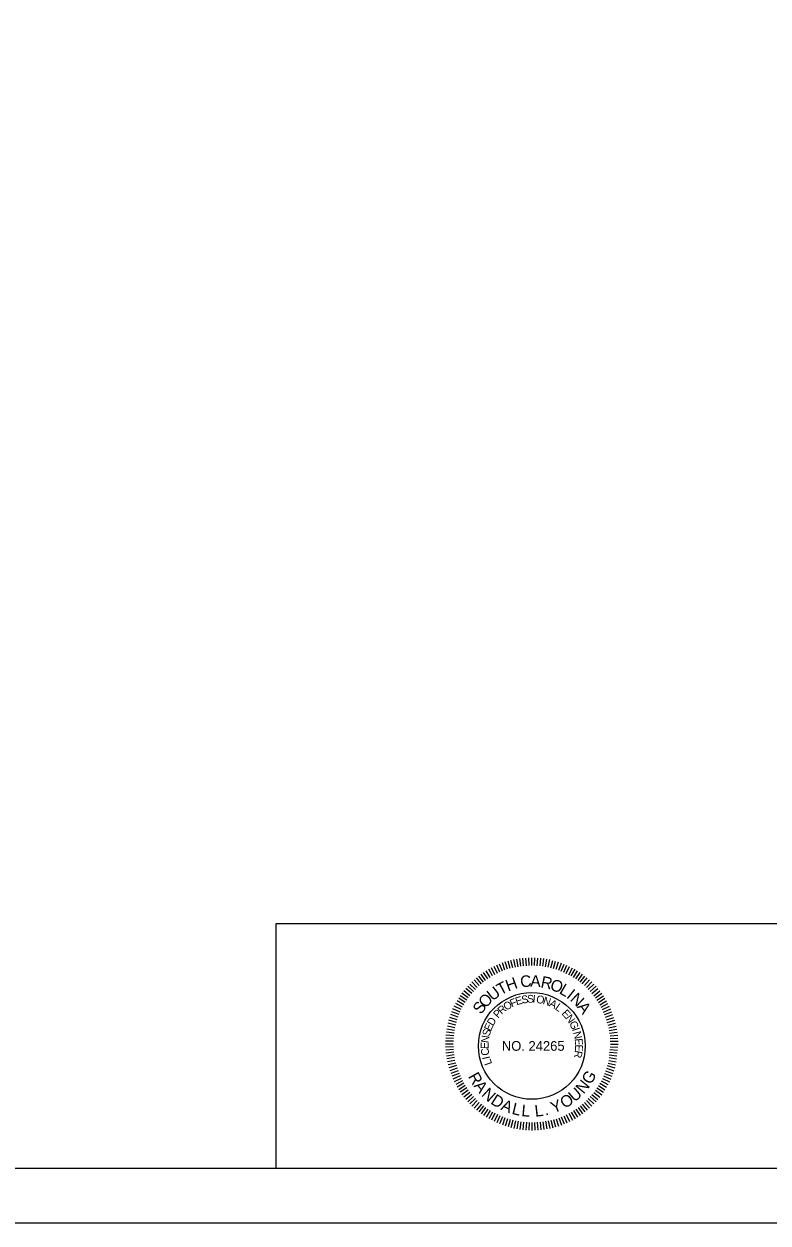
# Model space of a CAD drawing. Extents: x -796 to 2793, y -4650 to 4425.
# Drawn here: x 1879 to 2221, y -3500 to -2950 of the extents above; entities that cross this region are included whole.
import ezdxf

# ---------------------------------------------------------------- set-up
doc = ezdxf.new("R2010")
doc.units = 0
for name, color, linetype in [('RD_EX_Misc', 7, 'Continuous'), ('RD_HC_CL', 7, 'Continuous'), ('RD_HC_Data', 7, 'Continuous')]:
    doc.layers.add(name, color=color, linetype=linetype)

msp = doc.modelspace()

# ---------------------------------------------------------------- linework, layer by layer
at = {"layer": 'RD_EX_Misc'}
for p, q in [((2096.52, -3385.54), (2094.96, -3382.34)), ((2096.52, -3385.54), (2094.96, -3382.34)), ((2097.64, -3384.97), (2096.19, -3381.71)), ((2097.64, -3384.97), (2096.19, -3381.71)), ((2098.81, -3384.52), (2097.48, -3381.22)), ((2098.81, -3384.52), (2097.48, -3381.22)), ((2099.98, -3384.07), (2098.77, -3380.72)), ((2099.98, -3384.07), (2098.77, -3380.72)), ((2101.16, -3383.62), (2100.06, -3380.23)), ((2101.16, -3383.62), (2100.06, -3380.23)), ((2102.37, -3383.29), (2101.39, -3379.87)), ((2102.37, -3383.29), (2101.39, -3379.87)), ((2103.59, -3382.96), (2102.73, -3379.51)), ((2103.59, -3382.96), (2102.73, -3379.51)), ((2104.8, -3382.64), (2104.06, -3379.16)), ((2104.8, -3382.64), (2104.06, -3379.16)), ((2106.05, -3382.44), (2105.43, -3378.94)), ((2106.05, -3382.44), (2105.43, -3378.94)), ((2107.29, -3382.25), (2106.79, -3378.72)), ((2107.29, -3382.25), (2106.79, -3378.72)), ((2108.53, -3382.05), (2108.16, -3378.51)), ((2108.53, -3382.05), (2108.16, -3378.51)), ((2109.79, -3381.98), (2109.54, -3378.44)), ((2109.79, -3381.98), (2109.54, -3378.44)), ((2111.04, -3381.92), (2110.92, -3378.36)), ((2111.04, -3381.92), (2110.92, -3378.36)), ((2112.3, -3381.85), (2112.3, -3378.29)), ((2112.3, -3381.85), (2112.3, -3378.29)), ((2113.55, -3381.92), (2113.68, -3378.36)), ((2113.55, -3381.92), (2113.68, -3378.36)), ((2114.81, -3381.98), (2115.06, -3378.44)), ((2114.81, -3381.98), (2115.06, -3378.44)), ((2116.07, -3382.05), (2116.44, -3378.51)), ((2116.07, -3382.05), (2116.44, -3378.51)), ((2117.31, -3382.25), (2117.8, -3378.72)), ((2117.31, -3382.25), (2117.8, -3378.72)), ((2118.55, -3382.44), (2119.17, -3378.94)), ((2118.55, -3382.44), (2119.17, -3378.94)), ((2119.79, -3382.64), (2120.53, -3379.16)), ((2119.79, -3382.64), (2120.53, -3379.16)), ((2119.79, -3382.64), (2120.53, -3379.16)), ((2121.01, -3382.96), (2121.87, -3379.51)), ((2121.01, -3382.96), (2121.87, -3379.51)), ((2121.01, -3382.96), (2121.87, -3379.51)), ((2122.22, -3383.29), (2123.2, -3379.87)), ((2122.22, -3383.29), (2123.2, -3379.87)), ((2122.22, -3383.29), (2123.2, -3379.87)), ((2123.44, -3383.62), (2124.54, -3380.23)), ((2123.44, -3383.62), (2124.54, -3380.23)), ((2123.44, -3383.62), (2124.54, -3380.23)), ((2124.61, -3384.07), (2125.83, -3380.72)), ((2124.61, -3384.07), (2125.83, -3380.72)), ((2124.61, -3384.07), (2125.83, -3380.72)), ((2125.78, -3384.52), (2127.12, -3381.22)), ((2125.78, -3384.52), (2127.12, -3381.22)), ((2125.78, -3384.52), (2127.12, -3381.22)), ((2126.96, -3384.97), (2128.41, -3381.71)), ((2126.96, -3384.97), (2128.41, -3381.71)), ((2126.96, -3384.97), (2128.41, -3381.71)), ((2128.08, -3385.54), (2129.64, -3382.34)), ((2128.08, -3385.54), (2129.64, -3382.34)), ((2128.08, -3385.54), (2129.64, -3382.34)), ((2089.16, -3390.32), (2086.87, -3387.59)), ((2089.16, -3390.32), (2086.87, -3387.59)), ((2090.13, -3389.53), (2087.94, -3386.72)), ((2090.13, -3389.53), (2087.94, -3386.72)), ((2091.11, -3388.73), (2089.02, -3385.85)), ((2091.11, -3388.73), (2089.02, -3385.85)), ((2092.17, -3388.05), (2090.18, -3385.1)), ((2092.17, -3388.05), (2090.18, -3385.1)), ((2093.22, -3387.37), (2091.34, -3384.35)), ((2093.22, -3387.37), (2091.34, -3384.35)), ((2094.28, -3386.68), (2092.5, -3383.6)), ((2094.28, -3386.68), (2092.5, -3383.6)), ((2095.4, -3386.11), (2093.73, -3382.97)), ((2095.4, -3386.11), (2093.73, -3382.97)), ((2129.2, -3386.11), (2130.87, -3382.97)), ((2129.2, -3386.11), (2130.87, -3382.97)), ((2129.2, -3386.11), (2130.87, -3382.97)), ((2130.32, -3386.68), (2132.1, -3383.6)), ((2130.32, -3386.68), (2132.1, -3383.6)), ((2130.32, -3386.68), (2132.1, -3383.6)), ((2131.38, -3387.37), (2133.26, -3384.35)), ((2131.38, -3387.37), (2133.26, -3384.35)), ((2131.38, -3387.37), (2133.26, -3384.35)), ((2132.43, -3388.05), (2134.42, -3385.1)), ((2132.43, -3388.05), (2134.42, -3385.1)), ((2132.43, -3388.05), (2134.42, -3385.1)), ((2133.48, -3388.73), (2135.58, -3385.85)), ((2133.48, -3388.73), (2135.58, -3385.85)), ((2133.48, -3388.73), (2135.58, -3385.85)), ((2134.46, -3389.53), (2136.65, -3386.72)), ((2134.46, -3389.53), (2136.65, -3386.72)), ((2134.46, -3389.53), (2136.65, -3386.72)), ((2135.44, -3390.32), (2137.72, -3387.59)), ((2135.44, -3390.32), (2137.72, -3387.59)), ((2135.44, -3390.32), (2137.72, -3387.59)), ((2084.72, -3394.75), (2082, -3392.47)), ((2084.72, -3394.75), (2082, -3392.47)), ((2085.51, -3393.78), (2082.87, -3391.4)), ((2085.51, -3393.78), (2082.87, -3391.4)), ((2086.4, -3392.89), (2083.84, -3390.42)), ((2086.4, -3392.89), (2083.84, -3390.42)), ((2087.29, -3392), (2084.82, -3389.44)), ((2087.29, -3392), (2084.82, -3389.44)), ((2088.18, -3391.11), (2085.8, -3388.46)), ((2088.18, -3391.11), (2085.8, -3388.46)), ((2136.42, -3391.11), (2138.8, -3388.46)), ((2136.42, -3391.11), (2138.8, -3388.46)), ((2136.42, -3391.11), (2138.8, -3388.46)), ((2137.31, -3392), (2139.78, -3389.44)), ((2137.31, -3392), (2139.78, -3389.44)), ((2137.31, -3392), (2139.78, -3389.44)), ((2138.2, -3392.89), (2140.75, -3390.42)), ((2138.2, -3392.89), (2140.75, -3390.42)), ((2138.2, -3392.89), (2140.75, -3390.42)), ((2139.08, -3393.78), (2141.73, -3391.4)), ((2139.08, -3393.78), (2141.73, -3391.4)), ((2139.08, -3393.78), (2141.73, -3391.4)), ((2139.88, -3394.75), (2142.6, -3392.47)), ((2139.88, -3394.75), (2142.6, -3392.47)), ((2139.88, -3394.75), (2142.6, -3392.47)), ((2081.08, -3399.87), (2078, -3398.09)), ((2081.08, -3399.87), (2078, -3398.09)), ((2081.77, -3398.82), (2078.75, -3396.93)), ((2081.77, -3398.82), (2078.75, -3396.93)), ((2082.45, -3397.76), (2079.5, -3395.78)), ((2082.45, -3397.76), (2079.5, -3395.78)), ((2083.14, -3396.71), (2080.26, -3394.62)), ((2083.14, -3396.71), (2080.26, -3394.62)), ((2083.93, -3395.73), (2081.13, -3393.54)), ((2083.93, -3395.73), (2081.13, -3393.54)), ((2140.67, -3395.73), (2143.47, -3393.54)), ((2140.67, -3395.73), (2143.47, -3393.54)), ((2140.67, -3395.73), (2143.47, -3393.54)), ((2141.46, -3396.71), (2144.34, -3394.62)), ((2141.46, -3396.71), (2144.34, -3394.62)), ((2141.46, -3396.71), (2144.34, -3394.62)), ((2142.14, -3397.76), (2145.09, -3395.78)), ((2142.14, -3397.76), (2145.09, -3395.78)), ((2142.14, -3397.76), (2145.09, -3395.78)), ((2142.83, -3398.82), (2145.84, -3396.93)), ((2142.83, -3398.82), (2145.84, -3396.93)), ((2142.83, -3398.82), (2145.84, -3396.93)), ((2143.51, -3399.87), (2146.6, -3398.09)), ((2143.51, -3399.87), (2146.6, -3398.09)), ((2143.51, -3399.87), (2146.6, -3398.09)), ((2078.47, -3405.58), (2075.13, -3404.37)), ((2078.47, -3405.58), (2075.13, -3404.37)), ((2078.92, -3404.41), (2075.62, -3403.08)), ((2078.92, -3404.41), (2075.62, -3403.08)), ((2079.37, -3403.24), (2076.12, -3401.79)), ((2079.37, -3403.24), (2076.12, -3401.79)), ((2079.94, -3402.11), (2076.74, -3400.56)), ((2079.94, -3402.11), (2076.74, -3400.56)), ((2080.51, -3400.99), (2077.37, -3399.33)), ((2080.51, -3400.99), (2077.37, -3399.33)), ((2144.09, -3400.99), (2147.22, -3399.33)), ((2144.09, -3400.99), (2147.22, -3399.33)), ((2144.09, -3400.99), (2147.22, -3399.33)), ((2144.66, -3402.11), (2147.85, -3400.56)), ((2144.66, -3402.11), (2147.85, -3400.56)), ((2144.66, -3402.11), (2147.85, -3400.56)), ((2145.23, -3403.24), (2148.48, -3401.79)), ((2145.23, -3403.24), (2148.48, -3401.79)), ((2145.23, -3403.24), (2148.48, -3401.79)), ((2145.68, -3404.41), (2148.97, -3403.08)), ((2145.68, -3404.41), (2148.97, -3403.08)), ((2145.68, -3404.41), (2148.97, -3403.08)), ((2146.13, -3405.58), (2149.47, -3404.37)), ((2146.13, -3405.58), (2149.47, -3404.37)), ((2146.13, -3405.58), (2149.47, -3404.37)), ((2077.04, -3410.4), (2073.56, -3409.66)), ((2077.04, -3410.4), (2073.56, -3409.66)), ((2077.37, -3409.19), (2073.92, -3408.33)), ((2077.37, -3409.19), (2073.92, -3408.33)), ((2077.69, -3407.97), (2074.27, -3406.99)), ((2077.69, -3407.97), (2074.27, -3406.99)), ((2078.02, -3406.76), (2074.63, -3405.66)), ((2078.02, -3406.76), (2074.63, -3405.66)), ((2146.58, -3406.76), (2149.96, -3405.66)), ((2146.58, -3406.76), (2149.96, -3405.66)), ((2146.58, -3406.76), (2149.96, -3405.66)), ((2146.9, -3407.97), (2150.32, -3406.99)), ((2146.9, -3407.97), (2150.32, -3406.99)), ((2146.9, -3407.97), (2150.32, -3406.99)), ((2147.23, -3409.19), (2150.68, -3408.33)), ((2147.23, -3409.19), (2150.68, -3408.33)), ((2147.23, -3409.19), (2150.68, -3408.33)), ((2147.56, -3410.4), (2151.04, -3409.66)), ((2147.56, -3410.4), (2151.04, -3409.66)), ((2147.56, -3410.4), (2151.04, -3409.66)), ((2076.38, -3415.38), (2072.84, -3415.14)), ((2076.38, -3415.38), (2072.84, -3415.14)), ((2076.45, -3414.13), (2072.91, -3413.76)), ((2076.45, -3414.13), (2072.91, -3413.76)), ((2076.65, -3412.89), (2073.13, -3412.39)), ((2076.65, -3412.89), (2073.13, -3412.39)), ((2076.84, -3411.64), (2073.34, -3411.03)), ((2076.84, -3411.64), (2073.34, -3411.03)), ((2147.75, -3411.64), (2151.25, -3411.03)), ((2147.75, -3411.64), (2151.25, -3411.03)), ((2147.75, -3411.64), (2151.25, -3411.03)), ((2147.95, -3412.89), (2151.47, -3412.39)), ((2147.95, -3412.89), (2151.47, -3412.39)), ((2147.95, -3412.89), (2151.47, -3412.39)), ((2148.15, -3414.13), (2151.69, -3413.76)), ((2148.15, -3414.13), (2151.69, -3413.76)), ((2148.15, -3414.13), (2151.69, -3413.76)), ((2148.21, -3415.38), (2151.76, -3415.14)), ((2148.21, -3415.38), (2151.76, -3415.14)), ((2148.21, -3415.38), (2151.76, -3415.14)), ((2076.25, -3417.9), (2072.69, -3417.9)), ((2076.25, -3417.9), (2072.69, -3417.9)), ((2076.32, -3416.64), (2072.77, -3416.52)), ((2076.32, -3416.64), (2072.77, -3416.52)), ((2076.32, -3419.15), (2072.77, -3419.28)), ((2076.32, -3419.15), (2072.77, -3419.28)), ((2076.38, -3420.41), (2072.84, -3420.66)), ((2076.38, -3420.41), (2072.84, -3420.66)), ((2148.08, -3420.4), (2151.61, -3420.65)), ((2148.08, -3420.4), (2151.61, -3420.65)), ((2148.21, -3419.15), (2151.76, -3419.27)), ((2148.21, -3419.15), (2151.76, -3419.27)), ((2148.28, -3416.64), (2151.83, -3416.52)), ((2148.28, -3416.64), (2151.83, -3416.52)), ((2148.28, -3416.64), (2151.83, -3416.52)), ((2148.34, -3417.9), (2151.9, -3417.9)), ((2148.34, -3417.9), (2151.9, -3417.9)), ((2148.34, -3417.9), (2151.9, -3417.9)), ((2076.45, -3421.66), (2072.91, -3422.04)), ((2076.45, -3421.66), (2072.91, -3422.04)), ((2076.65, -3422.91), (2073.13, -3423.4)), ((2076.65, -3422.91), (2073.13, -3423.4)), ((2076.84, -3424.15), (2073.34, -3424.76)), ((2076.84, -3424.15), (2073.34, -3424.76)), ((2077.04, -3425.39), (2073.56, -3426.13)), ((2077.04, -3425.39), (2073.56, -3426.13)), ((2147.56, -3425.39), (2151.04, -3426.13)), ((2147.56, -3425.39), (2151.04, -3426.13)), ((2147.69, -3424.14), (2151.18, -3424.75)), ((2147.69, -3424.14), (2151.18, -3424.75)), ((2147.82, -3422.89), (2151.33, -3423.38)), ((2147.82, -3422.89), (2151.33, -3423.38)), ((2147.95, -3421.64), (2151.47, -3422.01)), ((2147.95, -3421.64), (2151.47, -3422.01)), ((2077.37, -3426.61), (2073.92, -3427.47)), ((2077.37, -3426.61), (2073.92, -3427.47)), ((2077.69, -3427.82), (2074.27, -3428.8)), ((2077.69, -3427.82), (2074.27, -3428.8)), ((2078.02, -3429.03), (2074.63, -3430.13)), ((2078.47, -3430.21), (2075.13, -3431.43)), ((2078.47, -3430.21), (2075.13, -3431.43)), ((2078.92, -3431.38), (2075.62, -3432.71)), ((2078.92, -3431.38), (2075.62, -3432.71)), ((2145.68, -3431.38), (2148.97, -3432.71)), ((2145.68, -3431.38), (2148.97, -3432.71)), ((2146.13, -3430.21), (2149.47, -3431.43)), ((2146.13, -3430.21), (2149.47, -3431.43)), ((2146.58, -3429.03), (2149.96, -3430.13)), ((2146.58, -3429.03), (2149.96, -3430.13)), ((2146.9, -3427.82), (2150.32, -3428.8)), ((2146.9, -3427.82), (2150.32, -3428.8)), ((2147.23, -3426.61), (2150.68, -3427.47)), ((2147.23, -3426.61), (2150.68, -3427.47)), ((2079.37, -3432.56), (2076.12, -3434)), ((2079.37, -3432.56), (2076.12, -3434)), ((2079.94, -3433.68), (2076.74, -3435.24)), ((2079.94, -3433.68), (2076.74, -3435.24)), ((2080.51, -3434.8), (2077.37, -3436.47)), ((2080.51, -3434.8), (2077.37, -3436.47)), ((2081.08, -3435.92), (2078, -3437.7)), ((2081.08, -3435.92), (2078, -3437.7)), ((2081.77, -3436.97), (2078.75, -3438.86)), ((2081.77, -3436.97), (2078.75, -3438.86)), ((2142.83, -3436.97), (2145.84, -3438.86)), ((2142.83, -3436.97), (2145.84, -3438.86)), ((2143.51, -3435.92), (2146.6, -3437.7)), ((2143.51, -3435.92), (2146.6, -3437.7)), ((2144.09, -3434.8), (2147.22, -3436.47)), ((2144.09, -3434.8), (2147.22, -3436.47)), ((2144.66, -3433.68), (2147.85, -3435.24)), ((2144.66, -3433.68), (2147.85, -3435.24)), ((2145.23, -3432.56), (2148.48, -3434)), ((2145.23, -3432.56), (2148.48, -3434)), ((2082.45, -3438.03), (2079.5, -3440.02)), ((2082.45, -3438.03), (2079.5, -3440.02)), ((2083.14, -3439.08), (2080.26, -3441.18)), ((2083.14, -3439.08), (2080.26, -3441.18)), ((2083.93, -3440.06), (2081.13, -3442.25)), ((2083.93, -3440.06), (2081.13, -3442.25)), ((2084.72, -3441.04), (2082, -3443.32)), ((2084.72, -3441.04), (2082, -3443.32)), ((2085.51, -3442.01), (2082.87, -3444.4)), ((2085.51, -3442.01), (2082.87, -3444.4)), ((2086.4, -3442.9), (2083.84, -3445.37)), ((2086.4, -3442.9), (2083.84, -3445.37)), ((2138.2, -3442.9), (2140.75, -3445.37)), ((2138.2, -3442.9), (2140.75, -3445.37)), ((2139.08, -3442.01), (2141.73, -3444.4)), ((2139.08, -3442.01), (2141.73, -3444.4)), ((2139.88, -3441.04), (2142.6, -3443.32)), ((2139.88, -3441.04), (2142.6, -3443.32)), ((2140.67, -3440.06), (2143.47, -3442.25)), ((2140.67, -3440.06), (2143.47, -3442.25)), ((2141.46, -3439.08), (2144.34, -3441.18)), ((2141.46, -3439.08), (2144.34, -3441.18)), ((2142.14, -3438.03), (2145.09, -3440.02)), ((2142.14, -3438.03), (2145.09, -3440.02)), ((2087.29, -3443.79), (2084.82, -3446.35)), ((2087.29, -3443.79), (2084.82, -3446.35)), ((2088.18, -3444.68), (2085.8, -3447.33)), ((2088.18, -3444.68), (2085.8, -3447.33)), ((2089.16, -3445.47), (2086.87, -3448.2)), ((2089.16, -3445.47), (2086.87, -3448.2)), ((2090.13, -3446.27), (2087.94, -3449.07)), ((2090.13, -3446.27), (2087.94, -3449.07)), ((2091.11, -3447.06), (2089.02, -3449.94)), ((2091.11, -3447.06), (2089.02, -3449.94)), ((2092.17, -3447.74), (2090.18, -3450.69)), ((2092.17, -3447.74), (2090.18, -3450.69)), ((2093.22, -3448.43), (2091.34, -3451.44)), ((2093.22, -3448.43), (2091.34, -3451.44)), ((2131.38, -3448.43), (2133.26, -3451.44)), ((2131.38, -3448.43), (2133.26, -3451.44)), ((2132.43, -3447.74), (2134.42, -3450.69)), ((2132.43, -3447.74), (2134.42, -3450.69)), ((2133.48, -3447.06), (2135.58, -3449.94)), ((2133.48, -3447.06), (2135.58, -3449.94)), ((2134.46, -3446.27), (2136.65, -3449.07)), ((2134.46, -3446.27), (2136.65, -3449.07)), ((2135.44, -3445.47), (2137.72, -3448.2)), ((2135.44, -3445.47), (2137.72, -3448.2)), ((2136.42, -3444.68), (2138.8, -3447.33)), ((2137.31, -3443.79), (2139.78, -3446.35)), ((2137.31, -3443.79), (2139.78, -3446.35)), ((2094.28, -3449.11), (2092.5, -3452.19)), ((2094.28, -3449.11), (2092.5, -3452.19)), ((2095.4, -3449.68), (2093.73, -3452.82)), ((2095.4, -3449.68), (2093.73, -3452.82)), ((2096.52, -3450.25), (2094.96, -3453.45)), ((2096.52, -3450.25), (2094.96, -3453.45)), ((2097.64, -3450.82), (2096.19, -3454.08)), ((2097.64, -3450.82), (2096.19, -3454.08)), ((2098.81, -3451.28), (2097.48, -3454.57)), ((2098.81, -3451.28), (2097.48, -3454.57)), ((2099.98, -3451.73), (2098.77, -3455.07)), ((2099.98, -3451.73), (2098.77, -3455.07)), ((2101.16, -3452.18), (2100.06, -3455.56)), ((2101.16, -3452.18), (2100.06, -3455.56)), ((2102.37, -3452.5), (2101.39, -3455.92)), ((2102.37, -3452.5), (2101.39, -3455.92)), ((2103.59, -3452.83), (2102.73, -3456.28)), ((2103.59, -3452.83), (2102.73, -3456.28)), ((2104.8, -3453.15), (2104.06, -3456.64)), ((2104.8, -3453.15), (2104.06, -3456.64)), ((2106.05, -3453.35), (2105.43, -3456.85)), ((2106.05, -3453.35), (2105.43, -3456.85)), ((2107.29, -3453.55), (2106.79, -3457.07)), ((2107.29, -3453.55), (2106.79, -3457.07)), ((2108.53, -3453.74), (2108.16, -3457.28)), ((2108.53, -3453.74), (2108.16, -3457.28)), ((2109.79, -3453.81), (2109.54, -3457.36)), ((2109.79, -3453.81), (2109.54, -3457.36)), ((2111.04, -3453.88), (2110.92, -3457.43)), ((2111.04, -3453.88), (2110.92, -3457.43)), ((2112.3, -3453.94), (2112.3, -3457.5)), ((2112.3, -3453.94), (2112.3, -3457.5)), ((2113.55, -3453.88), (2113.68, -3457.43)), ((2113.55, -3453.88), (2113.68, -3457.43)), ((2114.81, -3453.81), (2115.06, -3457.36)), ((2114.81, -3453.81), (2115.06, -3457.36)), ((2116.07, -3453.74), (2116.44, -3457.28)), ((2116.07, -3453.74), (2116.44, -3457.28)), ((2117.31, -3453.55), (2117.8, -3457.07)), ((2117.31, -3453.55), (2117.8, -3457.07)), ((2118.55, -3453.35), (2119.17, -3456.85)), ((2118.55, -3453.35), (2119.17, -3456.85)), ((2119.79, -3453.15), (2120.53, -3456.64)), ((2119.79, -3453.15), (2120.53, -3456.64)), ((2121.01, -3452.83), (2121.87, -3456.28)), ((2121.01, -3452.83), (2121.87, -3456.28)), ((2122.22, -3452.5), (2123.2, -3455.92)), ((2122.22, -3452.5), (2123.2, -3455.92)), ((2123.44, -3452.18), (2124.54, -3455.56)), ((2123.44, -3452.18), (2124.54, -3455.56)), ((2124.61, -3451.73), (2125.83, -3455.07)), ((2124.61, -3451.73), (2125.83, -3455.07)), ((2125.78, -3451.28), (2127.12, -3454.57)), ((2125.78, -3451.28), (2127.12, -3454.57)), ((2126.96, -3450.82), (2128.41, -3454.08)), ((2126.96, -3450.82), (2128.41, -3454.08)), ((2128.08, -3450.25), (2129.64, -3453.45)), ((2128.08, -3450.25), (2129.64, -3453.45)), ((2129.2, -3449.68), (2130.87, -3452.82)), ((2129.2, -3449.68), (2130.87, -3452.82)), ((2130.32, -3449.11), (2132.1, -3452.19)), ((2130.32, -3449.11), (2132.1, -3452.19))]:
    msp.add_line(p, q, dxfattribs=at)
msp.add_circle((2112.3, -3418.77), 24.48, dxfattribs=at)
at = {"layer": 'RD_HC_CL'}
msp.add_lwpolyline([(981.4, -2400), (2777.4, -2400), (2777.4, -3500), (981.4, -3500)], close=True, dxfattribs=at)
at = {"layer": 'RD_HC_Data'}
for p, q in [((1995.01, -3362.55), (2757.6, -3362.55)), ((1995.01, -3475), (1995.01, -3362.55)), ((2760, -3500), (1000, -3500)), ((2760, -3500), (1000, -3500))]:
    msp.add_line(p, q, dxfattribs=at)
msp.add_lwpolyline([(1082.6, -2425), (2757.6, -2425), (2757.6, -3475), (1082.6, -3475)], close=True, dxfattribs=at)

# ---------------------------------------------------------------- texts
at = {"layer": 'RD_EX_Misc'}
for s, height, rotation, p in [('H', 5.34, 19.9102, (2101.39, -3393.85)), ('C', 5.34, 6.8832, (2107.29, -3392.04)), ('A', 5.34, 357.9448, (2111.51, -3391.58)), ('R', 5.34, 348.267, (2116.09, -3391.84)), ('U', 5.34, 37.7726, (2094.28, -3398.4)), ('T', 5.34, 28.0947, (2097.96, -3395.66)), ('O', 5.34, 339.3286, (2120.23, -3392.75)), ('L', 5.34, 329.6507, (2124.49, -3394.46)), ('I', 5.34, 321.4663, (2127.83, -3396.44)), ('S', 5.34, 54.9027, (2089.07, -3404.61)), ('O', 5.34, 47.4504, (2091.11, -3401.72)), ('O', 3.56, 31.7869, (2100.54, -3402.71)), ('F', 3.56, 23.0853, (2103.11, -3401.12)), ('E', 3.56, 16.1843, (2105.3, -3400.14)), ('S', 3.56, 8.6909, (2107.79, -3399.39)), ('S', 3.56, 1.79, (2110.15, -3398.98)), ('I', 3.56, 354.889, (2112.54, -3398.87)), ('O', 3.56, 350.4045, (2114.1, -3398.95)), ('N', 3.56, 341.7029, (2117.08, -3399.45)), ('A', 3.56, 333.0013, (2119.94, -3400.4)), ('N', 5.34, 317.0007, (2129.52, -3397.72)), ('P', 3.56, 46.7912, (2096.78, -3406.3)), ('R', 3.56, 39.8902, (2098.4, -3404.53)), ('L', 3.56, 324.2997, (2122.64, -3401.76)), ('E', 3.56, 313.2251, (2125.71, -3404.07)), ('N', 3.56, 305.7317, (2127.52, -3405.94)), ('A', 5.34, 307.3229, (2132.81, -3400.91)), ('E', 3.56, 66.5674, (2093.48, -3412.29)), ('D', 3.56, 59.074, (2094.49, -3409.89)), ('G', 3.56, 297.0301, (2129.28, -3408.39)), ('N', 3.56, 82.17, (2092.43, -3417.59)), ('S', 3.56, 73.4683, (2092.84, -3414.59)), ('I', 3.56, 288.3285, (2130.66, -3411.08)), ('N', 3.56, 283.8441, (2131.2, -3412.54)), ('E', 3.56, 89.6633, (2092.44, -3420.19)), ('C', 3.56, 97.7667, (2092.84, -3422.97)), ('E', 3.56, 275.1424, (2131.93, -3415.47)), ('E', 3.56, 267.6491, (2132.19, -3418.06)), ('I', 3.56, 102.2511, (2093.23, -3424.48)), ('L', 3.56, 109.7445, (2094.13, -3426.92)), ('R', 3.56, 260.1557, (2132.11, -3420.66)), ('R', 5.34, 299.1493, (2082.9, -3432.75)), ('G', 5.34, 60.1113, (2139.41, -3436.8)), ('A', 5.34, 308.0877, (2085.42, -3437.15)), ('N', 5.34, 50.4335, (2135.99, -3441.1)), ('N', 5.34, 317.7655, (2088.89, -3441.4)), ('D', 5.34, 327.4433, (2093.03, -3445.01)), ('O', 5.34, 31.0778, (2127.25, -3447.69)), ('U', 5.34, 40.7556, (2131.9, -3444.76)), ('A', 5.34, 337.1212, (2097.72, -3447.88)), ('L', 5.34, 346.799, (2102.82, -3449.92)), ('L', 5.34, 354.9835, (2107.35, -3450.95)), ('L', 5.34, 6.5171, (2113.88, -3451.29)), ('Y', 5.34, 21.4, (2122.18, -3449.79)), ('.', 5.34, 14.7016, (2118.49, -3450.73))]:
    msp.add_text(s, height=height, rotation=rotation, dxfattribs=at).set_placement(p)
msp.add_text('NO. 24265', height=4.45, dxfattribs=at).set_placement((2098.54, -3421))

doc.saveas('drawing.dxf')
